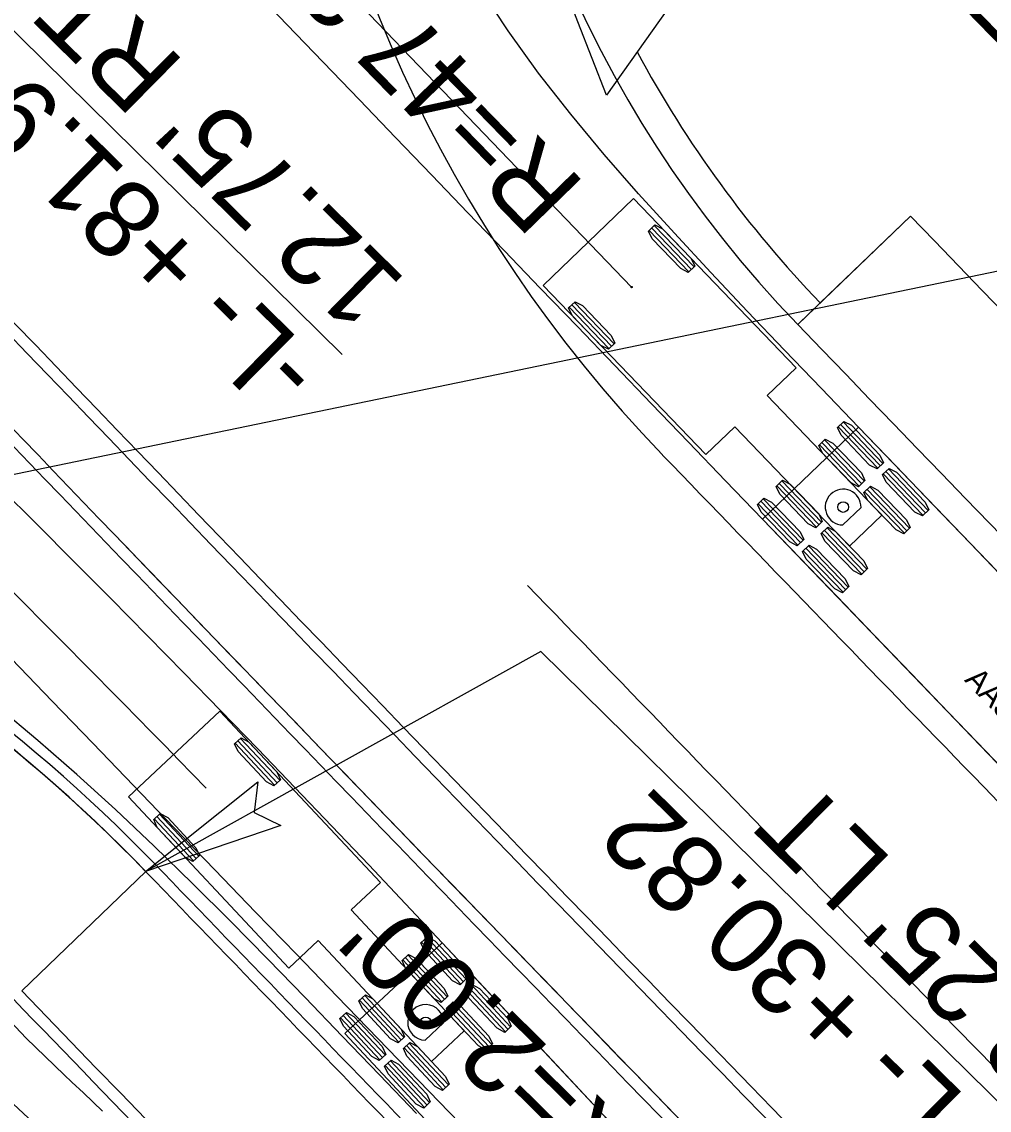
# Model space of a CAD drawing. Extents: x 1262642 to 1268358, y 767825 to 773481.
# Drawn here: x 1266830.8 to 1266892.6, y 772090.6 to 772160.2 of the extents above; entities that cross this region are included whole.
import ezdxf

# ---------------------------------------------------------------- set-up
doc = ezdxf.new("R2010")
doc.units = 0
for name, color, linetype in [('Old_Level_20', 7, 'Continuous'), ('Prop Conc 1ft 6in Curb and Gutter', 7, 'Continuous'), ('Prop Conc 2ft 6in Curb and Gutter', 7, 'Continuous'), ('Prop Conc 5in Monolithic Keyed In Island', 7, 'Continuous'), ('Prop Dimension', 7, 'Continuous'), ('Prop Dimension Text', 7, 'Continuous'), ('Prop EOT', 7, 'Continuous'), ('Prop Horizontal Alignment', 7, 'Continuous'), ('Prop Lane Lines', 7, 'Continuous'), ('Prop Paved Shoulder', 7, 'Continuous'), ('Prop Shade Light', 7, 'Continuous'), ('Prop Shade Medium', 7, 'Continuous'), ('Prop Terminator CELL', 7, 'Continuous'), ('Scratch_Level_3', 7, 'Continuous')]:
    doc.layers.add(name, color=color, linetype=linetype)

msp = doc.modelspace()

# ---------------------------------------------------------------- linework, layer by layer
at = {"layer": 'Old_Level_20'}
for p, q in [((1266866.287, 772160.205), (1266863.026, 772168.588)), ((1266873.527, 772163.15), (1266868.107, 772155.527)), ((1266868.107, 772155.527), (1266866.287, 772160.205))]:
    msp.add_line(p, q, dxfattribs=at)
at = {"layer": 'Prop Conc 1ft 6in Curb and Gutter'}
msp.add_arc((1275047.307, 780021.225), 11414.25, 223.9578669, 225.4193188, dxfattribs=at)
at = {"layer": 'Prop Conc 2ft 6in Curb and Gutter'}
msp.add_line((1266880.334, 772140.847), (1266881.774, 772142.235), dxfattribs=at)
msp.add_arc((1266934.351, 772192.878), 73, 208.28579, 223.92648, dxfattribs=at)
at = {"layer": 'Prop Conc 5in Monolithic Keyed In Island'}
msp.add_line((1266830.753, 772098.262), (1266838.671, 772105.898), dxfattribs=at)
for centre, radius, start, end in [((1275047.307, 780021.225), 11385.75, 223.6505027, 224.2564693), ((1275047.307, 780021.225), 11389.75, 223.8019285, 224.2564698), ((1275047.307, 780021.225), 11389.75, 223.87202, 224.2564698), ((1266767.185, 772036.948), 99.319, 43.95043, 64.95755), ((1275047.307, 780021.225), 11403.25, 223.9579874, 224.2224607)]:
    msp.add_arc(centre, radius, start, end, dxfattribs=at)
at = {"layer": 'Prop Dimension Text'}
for p, q in [((1266851.227, 772138.936), (1266824.646, 772165.127)), ((1266893.94, 772090.386), (1266863.925, 772119.96))]:
    msp.add_line(p, q, dxfattribs=at)
for points in [[(1266948.393, 772155.686), (1266809.22, 772126.931)], [(1266863.925, 772119.96), (1266838.666, 772105.893)]]:
    msp.add_lwpolyline(points, dxfattribs=at)
at = {"layer": 'Prop EOT'}
for centre, radius, start, end in [((1266934.351, 772192.878), 75, 137.90382, 223.92648), ((1275047.307, 780021.225), 11385, 223.6505027, 224.2564693), ((1275047.307, 780021.225), 11349, 223.9768445, 225.4019123), ((1275047.307, 780021.225), 11390.5, 223.8019285, 224.2564693), ((1266767.226, 772037.005), 100, 43.95786, 64.96497), ((1275047.307, 780021.225), 11402.5, 223.9578586, 224.2223874), ((1275047.307, 780021.225), 11415, 223.9578709, 224.2520264), ((1266699.67, 771910.536), 200, 44.17518, 66.65746)]:
    msp.add_arc(centre, radius, start, end, dxfattribs=at)
at = {"layer": 'Prop Horizontal Alignment'}
msp.add_arc((1275047.307, 780021.225), 11400, 222.9935866, 225.4043192, dxfattribs=at)
at = {"layer": 'Prop Lane Lines'}
for centre, radius, start, end in [((1266934.351, 772192.878), 87, 146.70968, 223.92648), ((1275047.307, 780021.225), 11427, 222.9935866, 225.3637298), ((1275047.307, 780021.225), 11361, 223.9768445, 224.2564693), ((1275047.307, 780021.225), 11373, 223.9768445, 224.2564693)]:
    msp.add_arc(centre, radius, start, end, dxfattribs=at)
at = {"layer": 'Prop Paved Shoulder'}
msp.add_line((1266881.774, 772142.235), (1266887.536, 772147.785), dxfattribs=at)
msp.add_arc((1275047.307, 780021.225), 11339, 223.9768889, 225.4019123, dxfattribs=at)
at = {"layer": 'Prop Shade Light'}
msp.add_line((1266887.537, 772147.784), (1266880.335, 772140.847), dxfattribs=at)
for centre, radius, start, end in [((1275047.307, 780021.225), 11339, 223.9768889, 225.401893), ((1275047.307, 780021.225), 11349, 223.9768445, 225.4019123), ((1266699.67, 771910.536), 200, 44.17518, 66.65746)]:
    msp.add_arc(centre, radius, start, end, dxfattribs=at)
at = {"layer": 'Prop Shade Medium'}
msp.add_line((1266830.753, 772098.262), (1266838.671, 772105.898), dxfattribs=at)
for centre, radius, start, end in [((1275047.307, 780021.225), 11385.75, 223.6505027, 224.2564693), ((1275047.307, 780021.225), 11389.75, 223.8019285, 224.2564698), ((1266767.226, 772037.005), 99.25, 43.95785, 64.96498)]:
    msp.add_arc(centre, radius, start, end, dxfattribs=at)
at = {"layer": 'Prop Terminator CELL'}
msp.add_lwpolyline([(1266847.31, 772108.838), (1266838.666, 772105.893), (1266845.847, 772111.628), (1266845.602, 772109.673)], close=True, dxfattribs=at)
at = {"layer": 'Scratch_Level_3'}
for p, q in [((1266869.722, 772143.248), (1266840.121, 772174.045)), ((1266869.834, 772148.904), (1266864.066, 772143.36)), ((1266880.228, 772138.089), (1266869.834, 772148.904)), ((1266870.839, 772146.865), (1266873.38, 772144.222)), ((1266871.005, 772147.024), (1266873.545, 772144.38)), ((1266871.17, 772147.183), (1266873.711, 772144.539)), ((1266864.066, 772143.36), (1266874.46, 772132.545)), ((1266864.066, 772143.36), (1266864.066, 772143.36)), ((1266865.733, 772141.957), (1266868.273, 772139.313)), ((1266865.898, 772142.116), (1266868.439, 772139.472)), ((1266866.063, 772142.274), (1266868.604, 772139.631)), ((1266878.378, 772136.311), (1266880.228, 772138.089)), ((1266885.712, 772128.68), (1266878.378, 772136.311)), ((1266874.46, 772132.545), (1266876.311, 772134.324)), ((1266876.311, 772134.324), (1266883.645, 772126.694)), ((1266882.909, 772134.308), (1266885.449, 772131.665)), ((1266883.074, 772134.467), (1266885.615, 772131.824)), ((1266883.239, 772134.626), (1266885.78, 772131.982)), ((1266884.22, 772134.297), (1266878.091, 772128.407)), ((1266917.482, 772099.691), (1266884.22, 772134.297)), ((1266881.719, 772133.165), (1266884.26, 772130.521)), ((1266881.884, 772133.324), (1266884.425, 772130.68)), ((1266882.049, 772133.483), (1266884.59, 772130.839)), ((1266886.126, 772131.622), (1266888.667, 772128.978)), ((1266879.322, 772130.861), (1266881.863, 772128.217)), ((1266885.796, 772131.304), (1266888.337, 772128.661)), ((1266885.961, 772131.463), (1266888.502, 772128.82)), ((1266878.991, 772130.543), (1266881.532, 772127.9)), ((1266879.157, 772130.702), (1266881.697, 772128.058)), ((1266884.606, 772130.161), (1266887.147, 772127.517)), ((1266884.772, 772130.32), (1266887.312, 772127.676)), ((1266884.937, 772130.479), (1266887.478, 772127.835)), ((1266877.967, 772129.559), (1266880.508, 772126.915)), ((1266878.132, 772129.717), (1266880.673, 772127.074)), ((1266877.802, 772129.4), (1266880.343, 772126.756)), ((1266883.212, 772128.046), (1266884.377, 772129.166)), ((1266878.091, 772128.407), (1266911.354, 772093.8)), ((1266878.091, 772128.407), (1266878.091, 772128.407)), ((1266883.645, 772126.694), (1266885.712, 772128.68)), ((1266881.879, 772127.539), (1266884.42, 772124.896)), ((1266882.044, 772127.698), (1266884.585, 772125.054)), ((1266882.209, 772127.857), (1266884.75, 772125.213)), ((1266881.019, 772126.713), (1266883.56, 772124.07)), ((1266880.689, 772126.396), (1266883.23, 772123.752)), ((1266880.854, 772126.555), (1266883.395, 772123.911)), ((1266843.418, 772116.138), (1266837.577, 772110.672)), ((1266853.668, 772105.186), (1266843.418, 772116.138)), ((1266844.564, 772114.243), (1266847.07, 772111.566)), ((1266844.732, 772114.4), (1266847.237, 772111.723)), ((1266844.397, 772114.087), (1266846.902, 772111.41)), ((1266837.577, 772110.672), (1266847.827, 772099.72)), ((1266837.577, 772110.672), (1266837.577, 772110.672)), ((1266839.393, 772109.403), (1266841.898, 772106.726)), ((1266839.56, 772109.56), (1266842.065, 772106.883)), ((1266839.225, 772109.247), (1266841.731, 772106.569)), ((1266851.794, 772103.433), (1266853.668, 772105.186)), ((1266859.026, 772095.705), (1266851.794, 772103.433)), ((1266856.633, 772101.683), (1266859.138, 772099.006)), ((1266847.827, 772099.72), (1266849.701, 772101.474)), ((1266849.701, 772101.474), (1266856.933, 772093.747)), ((1266857.609, 772101.342), (1266851.403, 772095.533)), ((1266856.298, 772101.37), (1266858.803, 772098.693)), ((1266856.465, 772101.527), (1266858.971, 772098.85)), ((1266890.408, 772066.295), (1266857.609, 772101.342)), ((1266855.093, 772100.243), (1266857.599, 772097.566)), ((1266855.261, 772100.399), (1266857.766, 772097.722)), ((1266855.428, 772100.556), (1266857.933, 772097.879)), ((1266859.145, 772098.328), (1266861.651, 772095.651)), ((1266859.312, 772098.485), (1266861.818, 772095.808)), ((1266859.48, 772098.641), (1266861.985, 772095.964)), ((1266852.331, 772097.658), (1266854.836, 772094.981)), ((1266852.498, 772097.814), (1266855.004, 772095.137)), ((1266852.666, 772097.971), (1266855.171, 772095.294)), ((1266858.275, 772097.514), (1266860.78, 772094.837)), ((1266851.461, 772096.843), (1266853.966, 772094.166)), ((1266857.94, 772097.201), (1266860.446, 772094.523)), ((1266858.108, 772097.357), (1266860.613, 772094.68)), ((1266851.126, 772096.53), (1266853.632, 772093.853)), ((1266851.293, 772096.687), (1266853.799, 772094.01)), ((1266856.518, 772095.105), (1266857.698, 772096.209)), ((1266851.403, 772095.533), (1266884.201, 772060.487)), ((1266851.403, 772095.533), (1266851.403, 772095.533)), ((1266856.933, 772093.747), (1266859.026, 772095.705)), ((1266855.345, 772094.772), (1266857.851, 772092.095)), ((1266855.513, 772094.929), (1266858.018, 772092.251)), ((1266855.178, 772094.615), (1266857.683, 772091.938)), ((1266853.973, 772093.488), (1266856.479, 772090.811)), ((1266854.141, 772093.645), (1266856.646, 772090.967)), ((1266854.308, 772093.801), (1266856.813, 772091.124))]:
    msp.add_line(p, q, dxfattribs=at)
for points in [[(1266894.723, 772111.104), (1266892.347, 772113.576), (1266889.971, 772116.047), (1266887.595, 772118.519), (1266885.219, 772120.991), (1266882.843, 772123.463), (1266880.467, 772125.935), (1266878.09, 772128.406), (1266875.72, 772130.866), (1266873.351, 772133.329), (1266870.986, 772135.794), (1266868.621, 772138.26), (1266866.253, 772140.723), (1266863.886, 772143.187), (1266863.886, 772143.187), (1266861.573, 772145.593), (1266859.261, 772147.999), (1266856.948, 772150.405), (1266854.635, 772152.811), (1266852.323, 772155.217), (1266850.01, 772157.623), (1266847.698, 772160.029), (1266845.4, 772162.449)], [(1266893.723, 772124.41), (1266891.347, 772126.881), (1266888.971, 772129.353), (1266886.596, 772131.825), (1266884.22, 772134.297), (1266884.22, 772134.297), (1266881.852, 772136.761), (1266879.487, 772139.227), (1266877.129, 772141.698), (1266874.783, 772144.182), (1266872.457, 772146.686), (1266870.164, 772149.218), (1266870.164, 772149.218), (1266867.968, 772151.731), (1266865.833, 772154.295), (1266863.777, 772156.924), (1266861.824, 772159.628), (1266859.996, 772162.419)], [(1266855.985, 772090.429), (1266853.612, 772092.905), (1266851.235, 772095.375), (1266848.861, 772097.832), (1266846.477, 772100.28), (1266844.081, 772102.715), (1266841.664, 772105.129), (1266839.218, 772107.514), (1266836.735, 772109.86), (1266836.735, 772109.86), (1266834.28, 772112.094), (1266831.78, 772114.272), (1266829.227, 772116.387), (1266826.618, 772118.431), (1266823.947, 772120.395), (1266821.215, 772122.27), (1266818.421, 772124.053), (1266815.569, 772125.74), (1266812.665, 772127.332), (1266809.716, 772128.827), (1266806.732, 772130.222), (1266803.724, 772131.515), (1266800.714, 772132.701), (1266798.928, 772133.354)], [(1266869.323, 772088.825), (1266866.98, 772091.328), (1266864.637, 772093.832), (1266862.294, 772096.335), (1266859.952, 772098.838), (1266857.609, 772101.342), (1266857.609, 772101.342), (1266855.271, 772103.833), (1266852.925, 772106.317), (1266850.571, 772108.794), (1266848.207, 772111.261), (1266845.838, 772113.724), (1266843.461, 772116.179), (1266843.461, 772116.179), (1266841.129, 772118.57), (1266838.79, 772120.955), (1266836.443, 772123.333), (1266834.089, 772125.703), (1266831.727, 772128.067), (1266829.359, 772130.423)], [(1266791.47, 772119.581), (1266793.471, 772119.384), (1266796.813, 772118.932), (1266800.167, 772118.113), (1266803.488, 772116.893), (1266806.745, 772115.46), (1266809.921, 772113.856), (1266813.009, 772112.086), (1266815.998, 772110.154), (1266818.826, 772107.988), (1266821.493, 772105.617), (1266824.007, 772103.084), (1266826.363, 772100.399), (1266828.673, 772097.733), (1266831.034, 772095.229), (1266833.472, 772092.899), (1266833.96, 772092.435)], [(1266833.96, 772092.435), (1266834.69, 772091.737), (1266835.903, 772090.57)]]:
    msp.add_lwpolyline(points, dxfattribs=at)
for points in [[(1266870.798, 772146.826), (1266871.211, 772147.222), (1266871.691, 772146.972), (1266873.52, 772145.068), (1266873.752, 772144.579), (1266873.339, 772144.182), (1266872.859, 772144.433), (1266871.03, 772146.336)], [(1266865.692, 772141.917), (1266866.104, 772142.314), (1266866.584, 772142.063), (1266868.413, 772140.16), (1266868.645, 772139.67), (1266868.232, 772139.274), (1266867.752, 772139.524), (1266865.923, 772141.428)], [(1266882.868, 772134.269), (1266883.28, 772134.665), (1266883.76, 772134.415), (1266885.589, 772132.511), (1266885.821, 772132.022), (1266885.408, 772131.625), (1266884.928, 772131.876), (1266883.099, 772133.779)], [(1266881.678, 772133.126), (1266882.09, 772133.522), (1266882.57, 772133.271), (1266884.4, 772131.368), (1266884.631, 772130.878), (1266884.219, 772130.482), (1266883.739, 772130.733), (1266881.909, 772132.636)], [(1266885.755, 772131.265), (1266886.167, 772131.661), (1266886.647, 772131.411), (1266888.477, 772129.507), (1266888.708, 772129.018), (1266888.296, 772128.621), (1266887.816, 772128.872), (1266885.986, 772130.775)], [(1266878.95, 772130.504), (1266879.363, 772130.9), (1266879.843, 772130.65), (1266881.672, 772128.746), (1266881.904, 772128.257), (1266881.491, 772127.86), (1266881.011, 772128.111), (1266879.182, 772130.014)], [(1266884.565, 772130.122), (1266884.978, 772130.518), (1266885.458, 772130.267), (1266887.287, 772128.364), (1266887.519, 772127.874), (1266887.106, 772127.478), (1266886.626, 772127.729), (1266884.797, 772129.632)], [(1266877.761, 772129.36), (1266878.173, 772129.757), (1266878.653, 772129.506), (1266880.483, 772127.603), (1266880.714, 772127.113), (1266880.302, 772126.717), (1266879.822, 772126.968), (1266877.992, 772128.871)], [(1266881.838, 772127.5), (1266882.25, 772127.896), (1266882.73, 772127.645), (1266884.559, 772125.742), (1266884.791, 772125.253), (1266884.379, 772124.856), (1266883.899, 772125.107), (1266882.069, 772127.01)], [(1266880.648, 772126.356), (1266881.06, 772126.753), (1266881.54, 772126.502), (1266883.37, 772124.599), (1266883.601, 772124.109), (1266883.189, 772123.713), (1266882.709, 772123.964), (1266880.88, 772125.867)], [(1266844.355, 772114.048), (1266844.773, 772114.439), (1266845.25, 772114.182), (1266847.054, 772112.254), (1266847.279, 772111.762), (1266846.861, 772111.371), (1266846.384, 772111.628), (1266844.58, 772113.555)], [(1266839.184, 772109.208), (1266839.601, 772109.599), (1266840.078, 772109.342), (1266841.882, 772107.414), (1266842.107, 772106.922), (1266841.689, 772106.531), (1266841.213, 772106.788), (1266839.409, 772108.715)], [(1266856.256, 772101.331), (1266856.674, 772101.722), (1266857.151, 772101.465), (1266858.955, 772099.538), (1266859.18, 772099.045), (1266858.762, 772098.654), (1266858.285, 772098.911), (1266856.481, 772100.839)], [(1266855.052, 772100.204), (1266855.469, 772100.595), (1266855.946, 772100.338), (1266857.75, 772098.41), (1266857.975, 772097.918), (1266857.557, 772097.527), (1266857.081, 772097.784), (1266855.277, 772099.711)], [(1266859.104, 772098.289), (1266859.521, 772098.68), (1266859.998, 772098.423), (1266861.802, 772096.496), (1266862.027, 772096.003), (1266861.609, 772095.612), (1266861.132, 772095.869), (1266859.328, 772097.797)], [(1266852.289, 772097.619), (1266852.707, 772098.01), (1266853.184, 772097.753), (1266854.988, 772095.825), (1266855.212, 772095.333), (1266854.795, 772094.942), (1266854.318, 772095.199), (1266852.514, 772097.126)], [(1266857.899, 772097.162), (1266858.316, 772097.553), (1266858.793, 772097.296), (1266860.597, 772095.368), (1266860.822, 772094.875), (1266860.404, 772094.485), (1266859.928, 772094.742), (1266858.124, 772096.669)], [(1266851.085, 772096.491), (1266851.502, 772096.882), (1266851.979, 772096.625), (1266853.783, 772094.698), (1266854.008, 772094.205), (1266853.59, 772093.814), (1266853.114, 772094.071), (1266851.31, 772095.999)], [(1266855.137, 772094.577), (1266855.554, 772094.967), (1266856.031, 772094.71), (1266857.835, 772092.783), (1266858.06, 772092.29), (1266857.642, 772091.899), (1266857.165, 772092.157), (1266855.361, 772094.084)], [(1266853.932, 772093.449), (1266854.349, 772093.84), (1266854.826, 772093.583), (1266856.63, 772091.655), (1266856.855, 772091.163), (1266856.437, 772090.772), (1266855.961, 772091.029), (1266854.157, 772092.957)]]:
    msp.add_lwpolyline(points, close=True, dxfattribs=at)
for centre, radius in [((1266869.722, 772143.248), 0.0417), ((1266883.234, 772129.189), 0.34), ((1266856.556, 772096.247), 0.34)]:
    msp.add_circle(centre, radius, dxfattribs=at)
for centre, radius, start, end in [((1266039.974, 771332.91), 1117.975, 44.120486, 46.184771), ((1266883.234, 772129.189), 1.143, 358.86541, 268.86541), ((1266856.556, 772096.247), 1.143, 358.10268, 268.10268), ((1266573.771, 771819.313), 373.618, 41.00041, 47.23753)]:
    msp.add_arc(centre, radius, start, end, dxfattribs=at)

# ---------------------------------------------------------------- texts
at = {"layer": 'Prop Dimension'}
for s, p in [("R=47.30'", (1266866.855, 772149.774)), ("R=75'", (1266903.265, 772155.571))]:
    msp.add_text(s, height=5, rotation=134.2575, dxfattribs=at).set_placement(p)
at = {"layer": 'Prop Dimension Text'}
for s, p in [("12.75' RT", (1266855.416, 772143.61)), ('-L- +81.99', (1266850.152, 772138.268)), ('-L- +30.82', (1266892.738, 772089.886)), ("3.25' LT", (1266898.002, 772095.228)), ("R=2.00'", (1266870.711, 772088.498))]:
    msp.add_text(s, height=5, rotation=135.42387, dxfattribs=at).set_placement(p)
at = {"layer": 'Scratch_Level_3'}
msp.add_text('AASHTO 2001 (US)', height=1.41667, rotation=313.86541, dxfattribs=at).set_placement((1266890.938, 772118.098))

doc.saveas('drawing.dxf')
